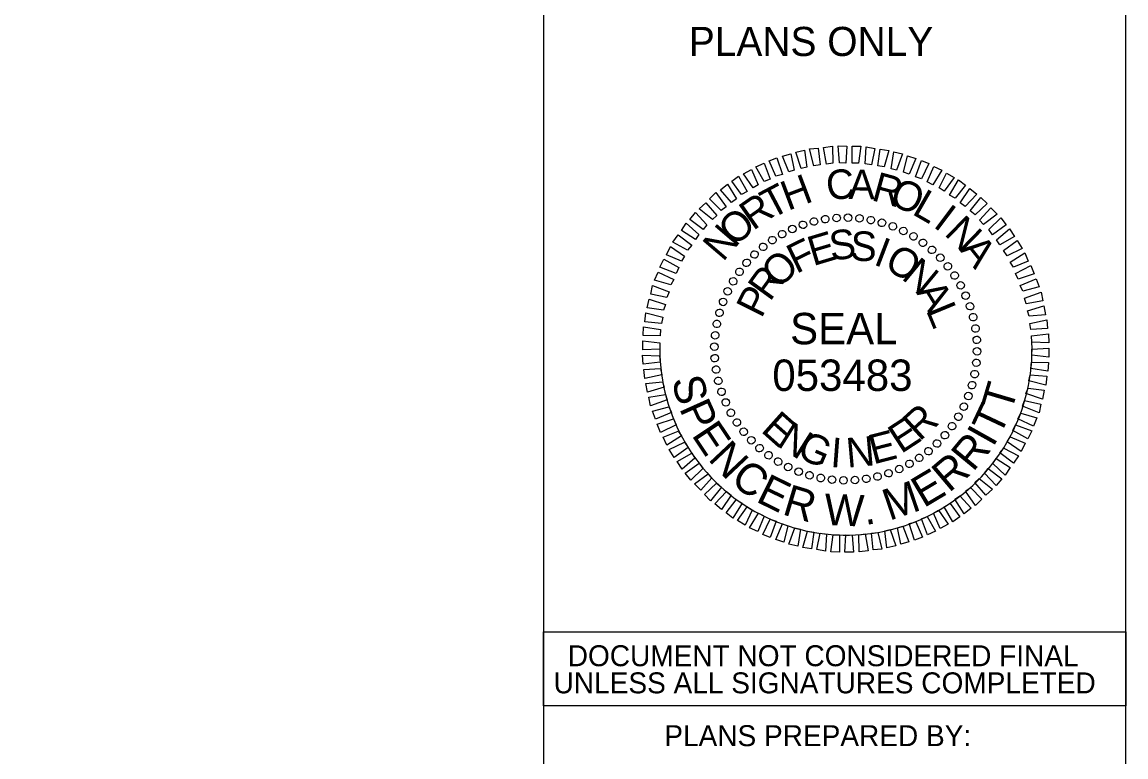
# Model space of a CAD drawing. Extents: x -0.71 to 3.09, y 0 to 1.8.
# Drawn here: x 2.4547 to 2.7708, y 1.3625 to 1.5729 of the extents above; entities that cross this region are included whole.
import ezdxf

# ---------------------------------------------------------------- set-up
doc = ezdxf.new("R2010")
doc.units = 0
for name, color, linetype in [('P_NCDOT_Horizontal_Alignment_Tick_Large', 7, 'Continuous'), ('P_NCDOT_Horizontal_Alignment_Tick_Small', 7, 'Continuous'), ('Prop Drainage Structure Bridge Opening', 7, 'Continuous'), ('Prop Plan Preparation Excavation Hatching', 7, 'Continuous')]:
    doc.layers.add(name, color=color, linetype=linetype)

msp = doc.modelspace()

# ---------------------------------------------------------------- linework, layer by layer
at = {"layer": 'P_NCDOT_Horizontal_Alignment_Tick_Large'}
msp.add_lwpolyline([(0.0625, 0.0625), (2.60412, 0.0625), (2.60412, 1.77083), (0.0625, 1.77083)], close=True, dxfattribs=at)
at = {"layer": 'P_NCDOT_Horizontal_Alignment_Tick_Small'}
for p, q in [((2.60412, 0.0625), (2.60416, 1.77083)), ((2.77079, 0.0625), (2.77083, 1.77083)), ((2.77082, 1.3771), (2.60405, 1.3771)), ((2.77082, 1.3771), (2.60405, 1.3771)), ((2.60405, 1.3771), (2.60405, 1.3771))]:
    msp.add_line(p, q, dxfattribs=at)
msp.add_lwpolyline([(2.60405, 1.39834), (2.77084, 1.39834), (2.77084, 1.3771), (2.60405, 1.3771)], close=True, dxfattribs=at)
at = {"layer": 'Prop Drainage Structure Bridge Opening'}
msp.add_arc((2.69065, 1.4793), 0.05331, 180.0118, 2.0847, dxfattribs=at)
at = {"layer": 'Prop Plan Preparation Excavation Hatching'}
for p, q in [((2.6783, 1.51491), (2.6783, 1.51491)), ((2.68145, 1.51581), (2.68145, 1.51581)), ((2.68475, 1.51641), (2.68475, 1.51641)), ((2.68797, 1.51686), (2.68797, 1.51686)), ((2.69127, 1.51694), (2.69127, 1.51694)), ((2.69457, 1.51671), (2.69457, 1.51671)), ((2.6978, 1.51619), (2.6978, 1.51619)), ((2.70095, 1.51551), (2.70095, 1.51551)), ((2.7041, 1.51446), (2.7041, 1.51446)), ((2.67237, 1.51221), (2.67237, 1.51221)), ((2.6753, 1.51371), (2.6753, 1.51371)), ((2.7071, 1.51311), (2.7071, 1.51311)), ((2.71002, 1.51161), (2.71002, 1.51161)), ((2.6669, 1.50861), (2.6669, 1.50861)), ((2.66952, 1.51049), (2.66952, 1.51049)), ((2.71272, 1.50974), (2.71272, 1.50974)), ((2.66442, 1.50636), (2.66442, 1.50636)), ((2.71535, 1.50771), (2.71535, 1.50771)), ((2.71767, 1.50546), (2.71767, 1.50546)), ((2.66217, 1.50404), (2.66217, 1.50404)), ((2.71992, 1.50299), (2.71992, 1.50299)), ((2.65827, 1.49871), (2.65827, 1.49871)), ((2.66015, 1.50141), (2.66015, 1.50141)), ((2.7218, 1.50036), (2.7218, 1.50036)), ((2.65677, 1.49579), (2.65677, 1.49579)), ((2.72352, 1.49751), (2.72352, 1.49751)), ((2.65542, 1.49279), (2.65542, 1.49279)), ((2.72502, 1.49459), (2.72502, 1.49459)), ((2.65437, 1.48964), (2.65437, 1.48964)), ((2.72622, 1.49159), (2.72622, 1.49159)), ((2.6537, 1.48649), (2.6537, 1.48649)), ((2.72712, 1.48844), (2.72712, 1.48844)), ((2.65317, 1.48326), (2.65317, 1.48326)), ((2.72772, 1.48514), (2.72772, 1.48514)), ((2.65295, 1.47996), (2.65295, 1.47996)), ((2.72817, 1.48191), (2.72817, 1.48191)), ((2.65302, 1.47666), (2.65302, 1.47666)), ((2.6906, 1.47929), (2.6906, 1.47929)), ((2.72825, 1.47861), (2.72825, 1.47861)), ((2.65347, 1.47344), (2.65347, 1.47344)), ((2.72802, 1.47531), (2.72802, 1.47531)), ((2.65407, 1.47014), (2.65407, 1.47014)), ((2.7275, 1.47209), (2.7275, 1.47209)), ((2.65497, 1.46699), (2.65497, 1.46699)), ((2.72682, 1.46894), (2.72682, 1.46894)), ((2.65617, 1.46399), (2.65617, 1.46399)), ((2.72577, 1.46579), (2.72577, 1.46579)), ((2.65767, 1.46106), (2.65767, 1.46106)), ((2.72442, 1.46279), (2.72442, 1.46279)), ((2.6594, 1.45821), (2.6594, 1.45821)), ((2.72292, 1.45986), (2.72292, 1.45986)), ((2.66127, 1.45559), (2.66127, 1.45559)), ((2.71902, 1.45454), (2.71902, 1.45454)), ((2.72105, 1.45716), (2.72105, 1.45716)), ((2.66352, 1.45311), (2.66352, 1.45311)), ((2.71677, 1.45221), (2.71677, 1.45221)), ((2.66585, 1.45086), (2.66585, 1.45086)), ((2.66847, 1.44884), (2.66847, 1.44884)), ((2.71167, 1.44809), (2.71167, 1.44809)), ((2.7143, 1.44996), (2.7143, 1.44996)), ((2.67117, 1.44696), (2.67117, 1.44696)), ((2.6741, 1.44546), (2.6741, 1.44546)), ((2.7059, 1.44486), (2.7059, 1.44486)), ((2.70882, 1.44636), (2.70882, 1.44636)), ((2.6771, 1.44411), (2.6771, 1.44411)), ((2.68025, 1.44306), (2.68025, 1.44306)), ((2.6834, 1.44239), (2.6834, 1.44239)), ((2.68662, 1.44186), (2.68662, 1.44186)), ((2.69322, 1.44171), (2.69322, 1.44171)), ((2.69645, 1.44216), (2.69645, 1.44216)), ((2.69975, 1.44276), (2.69975, 1.44276)), ((2.7029, 1.44366), (2.7029, 1.44366)), ((2.68992, 1.44164), (2.68992, 1.44164))]:
    msp.add_line(p, q, dxfattribs=at)
for points in [[(2.68145, 1.53179), (2.68025, 1.53659), (2.68272, 1.53681), (2.68325, 1.53201)], [(2.68505, 1.53224), (2.68422, 1.53704), (2.68677, 1.53734), (2.68685, 1.53246)], [(2.6888, 1.53261), (2.68842, 1.53749), (2.6909, 1.53741), (2.6906, 1.53254)], [(2.6924, 1.53254), (2.6924, 1.53741), (2.69487, 1.53734), (2.6942, 1.53246)], [(2.69615, 1.53231), (2.69645, 1.53719), (2.69892, 1.53674), (2.69795, 1.53201)], [(2.69975, 1.53171), (2.70042, 1.53651), (2.7029, 1.53614), (2.70155, 1.53149)], [(2.67057, 1.52879), (2.66862, 1.53314), (2.67087, 1.53404), (2.67245, 1.52924)], [(2.67425, 1.52999), (2.67252, 1.53449), (2.67485, 1.53516), (2.67582, 1.53051)], [(2.67785, 1.53096), (2.67627, 1.53569), (2.67882, 1.53621), (2.67942, 1.53134)], [(2.70357, 1.53089), (2.70432, 1.53576), (2.70687, 1.53516), (2.70515, 1.53051)], [(2.70717, 1.52991), (2.7083, 1.53456), (2.71062, 1.53381), (2.70875, 1.52939)], [(2.66405, 1.52541), (2.66127, 1.52946), (2.6636, 1.53066), (2.66547, 1.52631)], [(2.66727, 1.52721), (2.66487, 1.53141), (2.6672, 1.53246), (2.66892, 1.52789)], [(2.71055, 1.52856), (2.71227, 1.53329), (2.71437, 1.53239), (2.71227, 1.52804)], [(2.71392, 1.52714), (2.7158, 1.53156), (2.71812, 1.53051), (2.71557, 1.52631)], [(2.66075, 1.52354), (2.65797, 1.52736), (2.65992, 1.52879), (2.6624, 1.52444)], [(2.71737, 1.52541), (2.7194, 1.52969), (2.72165, 1.52841), (2.7188, 1.52451)], [(2.7203, 1.52339), (2.72292, 1.52774), (2.72487, 1.52616), (2.72195, 1.52249)], [(2.6549, 1.51896), (2.6516, 1.52226), (2.6534, 1.52406), (2.65632, 1.52001)], [(2.6579, 1.52129), (2.65467, 1.52489), (2.6567, 1.52646), (2.65932, 1.52226)], [(2.72337, 1.52114), (2.72615, 1.52526), (2.7281, 1.52361), (2.7248, 1.52009)], [(2.65242, 1.51634), (2.6486, 1.51941), (2.65047, 1.52114), (2.65362, 1.51754)], [(2.72622, 1.51881), (2.7293, 1.52271), (2.7311, 1.52091), (2.72765, 1.51769)], [(2.6498, 1.51349), (2.6459, 1.51641), (2.64755, 1.51836), (2.65085, 1.51484)], [(2.72892, 1.51619), (2.73215, 1.51971), (2.73395, 1.51791), (2.73005, 1.51499)], [(2.64755, 1.51064), (2.6435, 1.51319), (2.64492, 1.51536), (2.64852, 1.51206)], [(2.73155, 1.51349), (2.735, 1.51686), (2.73657, 1.51484), (2.7326, 1.51199)], [(2.6453, 1.50764), (2.6411, 1.50989), (2.6426, 1.51199), (2.6465, 1.50899)], [(2.7338, 1.51056), (2.73747, 1.51371), (2.7389, 1.51154), (2.7347, 1.50914)], [(2.6435, 1.50441), (2.63922, 1.50629), (2.64035, 1.50861), (2.6444, 1.50584)], [(2.73575, 1.50749), (2.73972, 1.51034), (2.74115, 1.50809), (2.7368, 1.50599)], [(2.642, 1.50096), (2.63735, 1.50269), (2.63847, 1.50501), (2.64275, 1.50261)], [(2.7377, 1.50419), (2.7419, 1.50681), (2.74287, 1.50449), (2.7386, 1.50276)], [(2.7392, 1.50096), (2.74362, 1.50321), (2.7446, 1.50081), (2.73995, 1.49931)], [(2.6405, 1.49766), (2.63585, 1.49901), (2.63682, 1.50134), (2.64132, 1.49924)], [(2.74055, 1.49744), (2.74512, 1.49939), (2.74595, 1.49706), (2.7413, 1.49586)], [(2.63937, 1.49406), (2.63472, 1.49504), (2.63525, 1.49751), (2.63997, 1.49564)], [(2.74175, 1.49384), (2.74655, 1.49556), (2.747, 1.49309), (2.74227, 1.49226)], [(2.6384, 1.49046), (2.63375, 1.49106), (2.63427, 1.49361), (2.639, 1.49204)], [(2.6378, 1.48664), (2.633, 1.48709), (2.6333, 1.48964), (2.63817, 1.48844)], [(2.74265, 1.49024), (2.74737, 1.49166), (2.74782, 1.48911), (2.7431, 1.48866)], [(2.74332, 1.48664), (2.7482, 1.48769), (2.74842, 1.48514), (2.74362, 1.48484)], [(2.63742, 1.48304), (2.63255, 1.48319), (2.6327, 1.48566), (2.63757, 1.48484)], [(2.74377, 1.48304), (2.74865, 1.48364), (2.7488, 1.48109), (2.74392, 1.48124)], [(2.63735, 1.47929), (2.63247, 1.47906), (2.63247, 1.48161), (2.63735, 1.48109)], [(2.63742, 1.47554), (2.63255, 1.47494), (2.6324, 1.47749), (2.63727, 1.47734)], [(2.74385, 1.47929), (2.74872, 1.47951), (2.74872, 1.47696), (2.74385, 1.47749)], [(2.63787, 1.47194), (2.633, 1.47089), (2.63277, 1.47344), (2.63757, 1.47374)], [(2.74377, 1.47554), (2.74865, 1.47539), (2.7485, 1.47291), (2.74362, 1.47374)], [(2.7434, 1.47194), (2.7482, 1.47149), (2.7479, 1.46894), (2.74302, 1.47014)], [(2.63855, 1.46834), (2.63382, 1.46691), (2.63337, 1.46946), (2.6381, 1.46991)], [(2.7428, 1.46811), (2.74745, 1.46751), (2.74692, 1.46496), (2.7422, 1.46654)], [(2.63945, 1.46474), (2.63465, 1.46301), (2.6342, 1.46549), (2.63892, 1.46631)], [(2.74182, 1.46451), (2.74647, 1.46354), (2.74595, 1.46106), (2.74122, 1.46294)], [(2.64065, 1.46114), (2.63607, 1.45919), (2.63525, 1.46151), (2.6399, 1.46271)], [(2.7407, 1.46091), (2.74535, 1.45956), (2.74437, 1.45724), (2.73987, 1.45934)], [(2.642, 1.45761), (2.63757, 1.45536), (2.6366, 1.45776), (2.64125, 1.45926)], [(2.7392, 1.45761), (2.74385, 1.45589), (2.74272, 1.45356), (2.73845, 1.45596)], [(2.6435, 1.45439), (2.6393, 1.45176), (2.63832, 1.45409), (2.6426, 1.45581)], [(2.64545, 1.45109), (2.64147, 1.44824), (2.64005, 1.45049), (2.6444, 1.45259)], [(2.7377, 1.45416), (2.74197, 1.45229), (2.74085, 1.44996), (2.7368, 1.45274)], [(2.6474, 1.44801), (2.64372, 1.44486), (2.6423, 1.44704), (2.6465, 1.44944)], [(2.7359, 1.45094), (2.7401, 1.44869), (2.7386, 1.44659), (2.7347, 1.44959)], [(2.64965, 1.44509), (2.6462, 1.44171), (2.64462, 1.44374), (2.6486, 1.44659)], [(2.7314, 1.44509), (2.7353, 1.44216), (2.73365, 1.44021), (2.73035, 1.44374)], [(2.73365, 1.44794), (2.7377, 1.44539), (2.73627, 1.44321), (2.73267, 1.44651)], [(2.65227, 1.44239), (2.64905, 1.43886), (2.64725, 1.44066), (2.65115, 1.44359)], [(2.72877, 1.44224), (2.7326, 1.43916), (2.73072, 1.43744), (2.72757, 1.44104)], [(2.65497, 1.43976), (2.6519, 1.43586), (2.6501, 1.43766), (2.65355, 1.44089)], [(2.7263, 1.43961), (2.7296, 1.43631), (2.7278, 1.43451), (2.72487, 1.43856)], [(2.65782, 1.43744), (2.65505, 1.43331), (2.6531, 1.43496), (2.6564, 1.43849)], [(2.6609, 1.43519), (2.65827, 1.43084), (2.65632, 1.43241), (2.65925, 1.43609)], [(2.7233, 1.43729), (2.72652, 1.43369), (2.7245, 1.43211), (2.72187, 1.43631)], [(2.66382, 1.43316), (2.6618, 1.42889), (2.65955, 1.43016), (2.6624, 1.43406)], [(2.66727, 1.43144), (2.6654, 1.42701), (2.66307, 1.42806), (2.66562, 1.43226)], [(2.71715, 1.43316), (2.71992, 1.42911), (2.7176, 1.42791), (2.71572, 1.43226)], [(2.72045, 1.43504), (2.72322, 1.43121), (2.72127, 1.42979), (2.7188, 1.43414)], [(2.67065, 1.43001), (2.66892, 1.42529), (2.66682, 1.42619), (2.66892, 1.43054)], [(2.67402, 1.42866), (2.6729, 1.42401), (2.67057, 1.42476), (2.67245, 1.42919)], [(2.71062, 1.42979), (2.71257, 1.42544), (2.71032, 1.42454), (2.70875, 1.42934)], [(2.71392, 1.43136), (2.71632, 1.42716), (2.714, 1.42611), (2.71227, 1.43069)], [(2.67762, 1.42769), (2.67687, 1.42281), (2.67432, 1.42341), (2.67605, 1.42806)], [(2.68145, 1.42686), (2.68077, 1.42206), (2.6783, 1.42244), (2.67965, 1.42709)], [(2.68505, 1.42626), (2.68475, 1.42139), (2.68227, 1.42184), (2.68325, 1.42656)], [(2.6888, 1.42604), (2.6888, 1.42116), (2.68632, 1.42124), (2.687, 1.42611)], [(2.6924, 1.42596), (2.69277, 1.42109), (2.6903, 1.42116), (2.6906, 1.42604)], [(2.69615, 1.42634), (2.69697, 1.42154), (2.69442, 1.42124), (2.69435, 1.42611)], [(2.69975, 1.42679), (2.70095, 1.42199), (2.69847, 1.42176), (2.69795, 1.42656)], [(2.70335, 1.42761), (2.70492, 1.42289), (2.70237, 1.42236), (2.70177, 1.42724)], [(2.70695, 1.42859), (2.70867, 1.42409), (2.70635, 1.42341), (2.70537, 1.42806)]]:
    msp.add_lwpolyline(points, close=True, dxfattribs=at)
for centre, major_axis in [((2.68471, 1.51645), (-0.00017, 0.00107)), ((2.68797, 1.51682), (-0.00008, 0.00108)), ((2.69125, 1.5169), (0.00002, 0.00108)), ((2.69453, 1.5167), (0.00011, 0.00107)), ((2.67529, 1.51366), (-0.000439, 0.000987)), ((2.67835, 1.51486), (-0.00035, 0.00102)), ((2.68149, 1.51579), (-0.00026, 0.00105)), ((2.69777, 1.51622), (0.00021, 0.00106)), ((2.70096, 1.51545), (0.0003, 0.00104)), ((2.70408, 1.51441), (0.00039, 0.00101)), ((2.66956, 1.51048), (-0.000604, 0.000895)), ((2.67236, 1.51219), (-0.000524, 0.000945)), ((2.70709, 1.5131), (0.000473, 0.000971)), ((2.70997, 1.51154), (0.000556, 0.000926)), ((2.66692, 1.50853), (-0.00068, 0.000839)), ((2.71271, 1.50972), (0.000635, 0.000874)), ((2.71528, 1.50768), (0.000709, 0.000815)), ((2.6622, 1.50397), (-0.000815, 0.000709)), ((2.66446, 1.50635), (-0.00075, 0.000777)), ((2.71766, 1.50542), (0.000777, 0.00075)), ((2.66016, 1.5014), (-0.000874, 0.000635)), ((2.71983, 1.50296), (0.000839, 0.00068)), ((2.65835, 1.49867), (-0.000926, 0.000556)), ((2.72178, 1.50033), (0.000895, 0.000604)), ((2.7235, 1.49753), (0.000945, 0.000524)), ((2.65678, 1.49578), (-0.000971, 0.000473)), ((2.72496, 1.49459), (0.000987, 0.000439)), ((2.65547, 1.49277), (-0.00101, 0.00039)), ((2.72617, 1.49154), (0.00102, 0.00035)), ((2.65443, 1.48966), (-0.00104, 0.0003)), ((2.7271, 1.48839), (0.00105, 0.00026)), ((2.65367, 1.48647), (-0.00106, 0.00021)), ((2.72775, 1.48517), (0.00107, 0.00017)), ((2.65318, 1.48322), (-0.00107, 0.00011)), ((2.72812, 1.48191), (0.00108, 0.00008)), ((2.65298, 1.47995), (-0.00108, 0.00002)), ((2.72821, 1.47863), (0.00108, -0.00002)), ((2.65307, 1.47667), (-0.00108, -0.00008)), ((2.72801, 1.47536), (0.00107, -0.00011)), ((2.65344, 1.4734), (-0.00107, -0.00017)), ((2.72752, 1.47211), (0.00106, -0.00021)), ((2.65409, 1.47019), (-0.00105, -0.00026)), ((2.72676, 1.46892), (0.00104, -0.0003)), ((2.65502, 1.46704), (-0.00102, -0.00035)), ((2.72572, 1.46581), (0.00101, -0.00039)), ((2.65623, 1.46399), (-0.000987, -0.000439)), ((2.72441, 1.4628), (0.000971, -0.000473)), ((2.65769, 1.46105), (-0.000945, -0.000524)), ((2.72284, 1.45991), (0.000926, -0.000556)), ((2.65941, 1.45825), (-0.000895, -0.000604)), ((2.72103, 1.45718), (0.000874, -0.000635)), ((2.66136, 1.45561), (-0.000839, -0.00068)), ((2.66353, 1.45316), (-0.000777, -0.00075)), ((2.71899, 1.45461), (0.000815, -0.000709)), ((2.66591, 1.4509), (-0.000709, -0.000815)), ((2.71427, 1.45005), (0.00068, -0.000839)), ((2.71673, 1.45223), (0.00075, -0.000777)), ((2.66848, 1.44885), (-0.000635, -0.000874)), ((2.67122, 1.44704), (-0.000556, -0.000926)), ((2.71163, 1.4481), (0.000604, -0.000895)), ((2.6741, 1.44548), (-0.000473, -0.000971)), ((2.67711, 1.44417), (-0.00039, -0.00101)), ((2.70284, 1.44372), (0.00035, -0.00102)), ((2.7059, 1.44492), (0.000439, -0.000987)), ((2.70883, 1.44639), (0.000524, -0.000945)), ((2.68023, 1.44313), (-0.0003, -0.00104)), ((2.68342, 1.44236), (-0.00021, -0.00106)), ((2.68666, 1.44188), (-0.00011, -0.00107)), ((2.68994, 1.44168), (-0.00002, -0.00108)), ((2.69322, 1.44176), (0.00008, -0.00108)), ((2.69648, 1.44213), (0.00017, -0.00107)), ((2.6997, 1.44279), (0.00026, -0.00105))]:
    msp.add_ellipse(centre, major_axis=major_axis, ratio=0.999708, dxfattribs=at)

# ---------------------------------------------------------------- texts
at = {"layer": 'P_NCDOT_Horizontal_Alignment_Tick_Small'}
for s, height, p in [('PLANS ONLY', 0.008339, (2.64563, 1.56319)), ('DOCUMENT NOT CONSIDERED FINAL', 0.0060042, (2.61097, 1.38846)), ('UNLESS ALL SIGNATURES COMPLETED', 0.0060042, (2.60692, 1.38069)), ('PLANS PREPARED BY:', 0.0060037, (2.63862, 1.36557))]:
    msp.add_text(s, height=height, rotation=0, dxfattribs=at).set_placement(p)
at = {"layer": 'Prop Plan Preparation Excavation Hatching'}
for s, height, rotation, p in [('C', 0.00846, 6.2199, (2.68542, 1.52181)), ('A', 0.00846, 359.0203, (2.69135, 1.52226)), ('H', 0.00846, 20.6195, (2.67402, 1.51881)), ('R', 0.00846, 344.6211, (2.69765, 1.52196)), ('O', 0.00846, 337.4212, (2.70267, 1.52084)), ('T', 0.00846, 27.8198, (2.66915, 1.51634)), ('L', 0.00846, 330.2209, (2.70927, 1.51806)), ('R', 0.00846, 35.0205, (2.66405, 1.51304)), ('O', 0.00846, 42.2217, (2.65887, 1.50839)), ('I', 0.00846, 323.0201, (2.71535, 1.51446)), ('N', 0.00846, 315.8189, (2.71857, 1.51214)), ('N', 0.00846, 49.4235, (2.65542, 1.50404)), ('E', 0.00846, 16.6111, (2.68122, 1.50299)), ('S', 0.00846, 7.2556, (2.6864, 1.50456)), ('S', 0.00846, 357.9004, (2.6918, 1.50464)), ('F', 0.00846, 25.967, (2.67642, 1.50074)), ('I', 0.00846, 339.1896, (2.69825, 1.50359)), ('O', 0.00846, 329.8335, (2.70125, 1.50254)), ('A', 0.00846, 308.6172, (2.723, 1.50771)), ('O', 0.00846, 44.6812, (2.67147, 1.49631)), ('N', 0.00846, 320.4766, (2.70627, 1.49954)), ('R', 0.00846, 54.0397, (2.66885, 1.49264)), ('P', 0.00846, 63.3989, (2.66645, 1.48784)), ('A', 0.00846, 301.7603, (2.71055, 1.49564)), ('L', 0.00846, 292.4009, (2.71347, 1.49046)), ('SEAL', 0.008997, 360, (2.67465, 1.48064)), ('S', 0.009, 284.7638, (2.64065, 1.47046)), ('T', 0.009, 73.4708, (2.73797, 1.46088)), ('P', 0.009, 294.2618, (2.64279, 1.46233)), ('T', 0.009, 64.7726, (2.73464, 1.45394)), ('E', 0.00846, 318.2769, (2.666, 1.45581)), ('R', 0.00846, 42.4814, (2.71175, 1.45266)), ('E', 0.009, 303.7599, (2.64625, 1.45467)), ('N', 0.00846, 327.634, (2.6705, 1.45176)), ('E', 0.00846, 33.1241, (2.70642, 1.44914)), ('G', 0.00846, 336.9902, (2.6762, 1.44839)), ('N', 0.00846, 5.0564, (2.69105, 1.44531)), ('E', 0.00846, 14.4118, (2.69847, 1.44621)), ('R', 0.009, 50.5372, (2.72705, 1.4439)), ('I', 0.009, 60.8196, (2.73279, 1.45096)), ('N', 0.009, 313.2579, (2.65092, 1.44768)), ('I', 0.00846, 355.7012, (2.68602, 1.44554)), ('R', 0.009, 40.2548, (2.72015, 1.43797)), ('C', 0.009, 323.5403, (2.6572, 1.44109)), ('E', 0.009, 30.7567, (2.71293, 1.43367)), ('E', 0.009, 333.8228, (2.66456, 1.43574)), ('R', 0.009, 343.3208, (2.67211, 1.43203)), ('M', 0.009, 18.8977, (2.70307, 1.43006)), ('W', 0.009, 357.5563, (2.6843, 1.42892)), ('.', 0.009, 10.9918, (2.69618, 1.42882))]:
    msp.add_text(s, height=height, rotation=rotation, dxfattribs=at).set_placement(p)
msp.add_text('053483', height=0.008997, dxfattribs=at).set_placement((2.66956, 1.46728))

doc.saveas('drawing.dxf')
